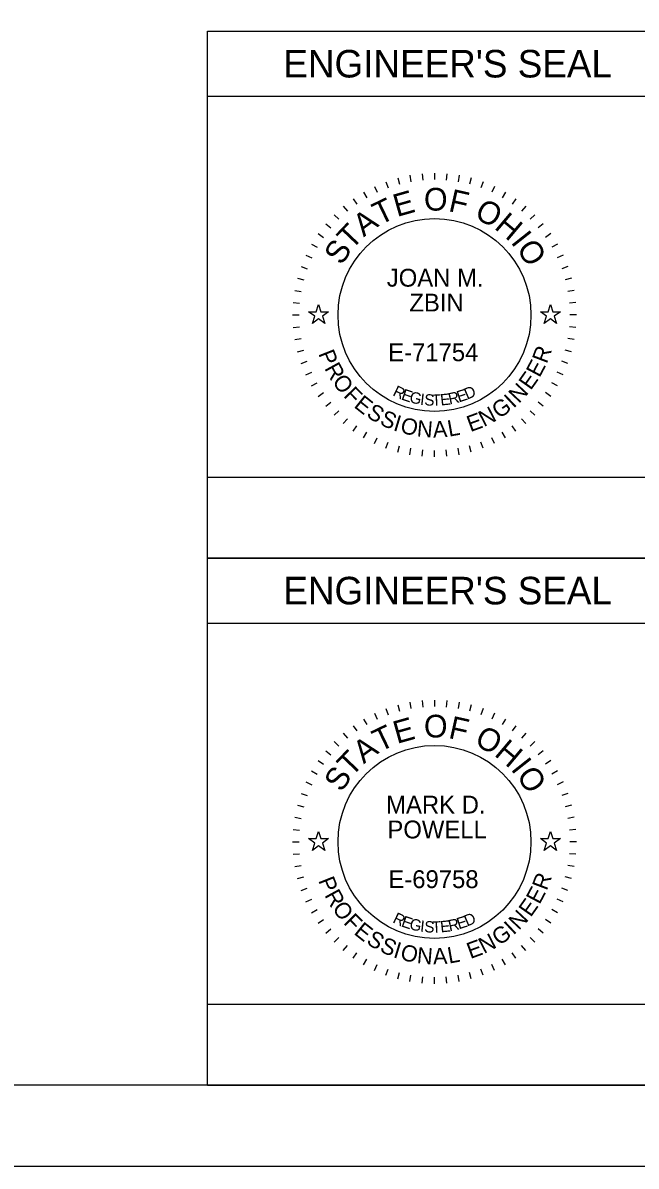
# Model space of a CAD drawing. Extents: x -6.1 to 38, y -7.7 to 22.
# Drawn here: x 7.31 to 11.09, y 0 to 7.05 of the extents above; entities that cross this region are included whole.
import ezdxf

# ---------------------------------------------------------------- set-up
doc = ezdxf.new("R2010")
doc.units = 0
for name, color, linetype in [('Default', 7, 'Continuous'), ('SH_Border', 7, 'Continuous'), ('SH_Cut_Line', 7, 'Continuous'), ('SH_Data', 7, 'Continuous')]:
    doc.layers.add(name, color=color, linetype=linetype)

msp = doc.modelspace()

# ---------------------------------------------------------------- linework, layer by layer
at = {"layer": 'Default'}
for points in [[(9.0736, 5.27), (9.1205, 5.27), (9.135, 5.3145), (9.1495, 5.27), (9.1964, 5.27), (9.1585, 5.2424), (9.173, 5.1978), (9.135, 5.2254), (9.097, 5.1978), (9.1115, 5.2424)], [(10.5036, 5.27), (10.5505, 5.27), (10.565, 5.3145), (10.5795, 5.27), (10.6264, 5.27), (10.5885, 5.2424), (10.603, 5.1978), (10.565, 5.2254), (10.527, 5.1978), (10.5415, 5.2424)], [(9.0736, 2.02), (9.1205, 2.02), (9.135, 2.0645), (9.1495, 2.02), (9.1964, 2.02), (9.1585, 1.9924), (9.173, 1.9478), (9.135, 1.9754), (9.097, 1.9478), (9.1115, 1.9924)], [(10.5036, 2.02), (10.5505, 2.02), (10.565, 2.0645), (10.5795, 2.02), (10.6264, 2.02), (10.5885, 1.9924), (10.603, 1.9478), (10.565, 1.9754), (10.527, 1.9478), (10.5415, 1.9924)]]:
    msp.add_lwpolyline(points, close=True, dxfattribs=at)
at = {"layer": 'SH_Border'}
msp.add_lwpolyline([(1.5, 21.5), (33.5, 21.5), (33.5, 0.5), (1.5, 0.5)], close=True, dxfattribs=at)
at = {"layer": 'SH_Cut_Line'}
msp.add_lwpolyline([(0, 0), (34, 0), (34, 22), (0, 22)], close=True, dxfattribs=at)
at = {"layer": 'SH_Data'}
for p, q in [((8.45, 3.75), (8.45, 7)), ((8.45, 7), (11.25, 7)), ((8.45, 6.6), (11.25, 6.6)), ((9.5507, 6.0722), (9.5644, 6.0346)), ((9.6235, 6.0952), (9.6339, 6.0565)), ((9.6981, 6.1117), (9.705, 6.0723)), ((9.7737, 6.1217), (9.7772, 6.0818)), ((9.85, 6.125), (9.85, 6.085)), ((9.9263, 6.1217), (9.9228, 6.0818)), ((10.0019, 6.1117), (9.995, 6.0723)), ((10.0765, 6.0952), (10.0661, 6.0565)), ((10.1493, 6.0722), (10.1356, 6.0346)), ((9.4125, 6.0078), (9.4325, 5.9731)), ((9.4802, 6.043), (9.4971, 6.0068)), ((10.2198, 6.043), (10.2029, 6.0068)), ((10.2875, 6.0078), (10.2675, 5.9731)), ((9.3481, 5.9668), (9.3711, 5.934)), ((10.3519, 5.9668), (10.3289, 5.934)), ((9.2313, 5.8687), (9.2596, 5.8404)), ((9.2876, 5.9203), (9.3133, 5.8896)), ((10.4124, 5.9203), (10.3867, 5.8896)), ((10.4687, 5.8687), (10.4404, 5.8404)), ((9.1797, 5.8124), (9.2104, 5.7867)), ((10.5203, 5.8124), (10.4896, 5.7867)), ((9.1332, 5.7519), (9.166, 5.7289)), ((10.5668, 5.7519), (10.534, 5.7289)), ((9.0922, 5.6875), (9.1269, 5.6675)), ((10.6078, 5.6875), (10.5731, 5.6675)), ((9.057, 5.6198), (9.0932, 5.6029)), ((10.643, 5.6198), (10.6068, 5.6029)), ((9.0278, 5.5493), (9.0654, 5.5356)), ((10.6722, 5.5493), (10.6346, 5.5356)), ((9.0048, 5.4765), (9.0435, 5.4661)), ((10.6952, 5.4765), (10.6565, 5.4661)), ((8.9883, 5.4019), (9.0277, 5.395)), ((10.7117, 5.4019), (10.6723, 5.395)), ((8.9783, 5.3263), (9.0182, 5.3228)), ((10.7217, 5.3263), (10.6818, 5.3228)), ((8.975, 5.25), (9.015, 5.25)), ((10.725, 5.25), (10.685, 5.25)), ((8.9783, 5.1737), (9.0182, 5.1772)), ((10.7217, 5.1737), (10.6818, 5.1772)), ((8.9883, 5.0981), (9.0277, 5.105)), ((10.7117, 5.0981), (10.6723, 5.105)), ((9.0048, 5.0235), (9.0435, 5.0339)), ((10.6952, 5.0235), (10.6565, 5.0339)), ((9.0278, 4.9507), (9.0654, 4.9644)), ((10.6722, 4.9507), (10.6346, 4.9644)), ((9.057, 4.8802), (9.0932, 4.8971)), ((10.643, 4.8802), (10.6068, 4.8971)), ((9.0922, 4.8125), (9.1269, 4.8325)), ((10.6078, 4.8125), (10.5731, 4.8325)), ((9.1332, 4.7481), (9.166, 4.7711)), ((10.5668, 4.7481), (10.534, 4.7711)), ((9.1797, 4.6876), (9.2104, 4.7133)), ((9.2313, 4.6313), (9.2596, 4.6596)), ((10.4687, 4.6313), (10.4404, 4.6596)), ((10.5203, 4.6876), (10.4896, 4.7133)), ((9.2876, 4.5797), (9.3133, 4.6104)), ((10.4124, 4.5797), (10.3867, 4.6104)), ((9.3481, 4.5332), (9.3711, 4.566)), ((9.4125, 4.4922), (9.4325, 4.5269)), ((10.2875, 4.4922), (10.2675, 4.5269)), ((10.3519, 4.5332), (10.3289, 4.566)), ((9.4802, 4.457), (9.4971, 4.4932)), ((9.5507, 4.4278), (9.5644, 4.4654)), ((9.6235, 4.4048), (9.6339, 4.4435)), ((10.0765, 4.4048), (10.0661, 4.4435)), ((10.1493, 4.4278), (10.1356, 4.4654)), ((10.2198, 4.457), (10.2029, 4.4932)), ((9.6981, 4.3883), (9.705, 4.4277)), ((9.7737, 4.3783), (9.7772, 4.4182)), ((9.85, 4.375), (9.85, 4.415)), ((9.9263, 4.3783), (9.9228, 4.4182)), ((10.0019, 4.3883), (9.995, 4.4277)), ((8.45, 3.75), (11.25, 3.75)), ((8.45, 3.75), (11.25, 3.75)), ((8.45, 0.5), (8.45, 3.75)), ((8.45, 3.75), (11.25, 3.75)), ((8.45, 3.35), (11.25, 3.35)), ((9.5507, 2.8222), (9.5644, 2.7846)), ((9.6235, 2.8452), (9.6339, 2.8065)), ((9.6981, 2.8617), (9.705, 2.8223)), ((9.7737, 2.8717), (9.7772, 2.8318)), ((9.85, 2.875), (9.85, 2.835)), ((9.9263, 2.8717), (9.9228, 2.8318)), ((10.0019, 2.8617), (9.995, 2.8223)), ((10.0765, 2.8452), (10.0661, 2.8065)), ((10.1493, 2.8222), (10.1356, 2.7846)), ((9.4125, 2.7578), (9.4325, 2.7231)), ((9.4802, 2.793), (9.4971, 2.7568)), ((10.2198, 2.793), (10.2029, 2.7568)), ((10.2875, 2.7578), (10.2675, 2.7231)), ((9.3481, 2.7168), (9.3711, 2.684)), ((10.3519, 2.7168), (10.3289, 2.684)), ((9.2313, 2.6187), (9.2596, 2.5904)), ((9.2876, 2.6703), (9.3133, 2.6396)), ((10.4124, 2.6703), (10.3867, 2.6396)), ((10.4687, 2.6187), (10.4404, 2.5904)), ((9.1797, 2.5624), (9.2104, 2.5367)), ((10.5203, 2.5624), (10.4896, 2.5367)), ((9.1332, 2.5019), (9.166, 2.4789)), ((10.5668, 2.5019), (10.534, 2.4789)), ((9.0922, 2.4375), (9.1269, 2.4175)), ((10.6078, 2.4375), (10.5731, 2.4175)), ((9.057, 2.3698), (9.0932, 2.3529)), ((10.643, 2.3698), (10.6068, 2.3529)), ((9.0278, 2.2993), (9.0654, 2.2856)), ((10.6722, 2.2993), (10.6346, 2.2856)), ((9.0048, 2.2265), (9.0435, 2.2161)), ((10.6952, 2.2265), (10.6565, 2.2161)), ((8.9883, 2.1519), (9.0277, 2.145)), ((10.7117, 2.1519), (10.6723, 2.145)), ((8.9783, 2.0763), (9.0182, 2.0728)), ((10.7217, 2.0763), (10.6818, 2.0728)), ((8.975, 2), (9.015, 2)), ((10.725, 2), (10.685, 2)), ((8.9783, 1.9237), (9.0182, 1.9272)), ((10.7217, 1.9237), (10.6818, 1.9272)), ((8.9883, 1.8481), (9.0277, 1.855)), ((10.7117, 1.8481), (10.6723, 1.855)), ((9.0048, 1.7735), (9.0435, 1.7839)), ((10.6952, 1.7735), (10.6565, 1.7839)), ((9.0278, 1.7007), (9.0654, 1.7144)), ((10.6722, 1.7007), (10.6346, 1.7144)), ((9.057, 1.6302), (9.0932, 1.6471)), ((10.643, 1.6302), (10.6068, 1.6471)), ((9.0922, 1.5625), (9.1269, 1.5825)), ((10.6078, 1.5625), (10.5731, 1.5825)), ((9.1332, 1.4981), (9.166, 1.5211)), ((10.5668, 1.4981), (10.534, 1.5211)), ((9.1797, 1.4376), (9.2104, 1.4633)), ((10.5203, 1.4376), (10.4896, 1.4633)), ((9.2313, 1.3813), (9.2596, 1.4096)), ((9.2876, 1.3297), (9.3133, 1.3604)), ((10.4124, 1.3297), (10.3867, 1.3604)), ((10.4687, 1.3813), (10.4404, 1.4096)), ((9.3481, 1.2832), (9.3711, 1.316)), ((9.4125, 1.2422), (9.4325, 1.2769)), ((10.2875, 1.2422), (10.2675, 1.2769)), ((10.3519, 1.2832), (10.3289, 1.316)), ((9.4802, 1.207), (9.4971, 1.2432)), ((9.5507, 1.1778), (9.5644, 1.2154)), ((10.1493, 1.1778), (10.1356, 1.2154)), ((10.2198, 1.207), (10.2029, 1.2432)), ((9.6235, 1.1548), (9.6339, 1.1935)), ((9.6981, 1.1383), (9.705, 1.1777)), ((9.7737, 1.1283), (9.7772, 1.1682)), ((9.85, 1.125), (9.85, 1.165)), ((9.9263, 1.1283), (9.9228, 1.1682)), ((10.0019, 1.1383), (9.995, 1.1777)), ((10.0765, 1.1548), (10.0661, 1.1935)), ((8.45, 0.5), (11.25, 0.5))]:
    msp.add_line(p, q, dxfattribs=at)
for points in [[(8.45, 3.75), (8.45, 4.25), (11.25, 4.25), (11.25, 3.75)], [(8.45, 0.5), (8.45, 1), (11.25, 1), (11.25, 0.5)]]:
    msp.add_lwpolyline(points, close=True, dxfattribs=at)
for centre in [(9.85, 5.25), (9.85, 2)]:
    msp.add_circle(centre, 0.595, dxfattribs=at)

# ---------------------------------------------------------------- texts
for s, height, p in [("ENGINEER'S SEAL", 0.17, (8.9176, 6.715)), ('JOAN M.', 0.11, (9.5559, 5.4249)), ('ZBIN', 0.11, (9.695, 5.2716)), ('E-71754', 0.11, (9.5645, 4.9651)), ("ENGINEER'S SEAL", 0.17, (8.9176, 3.465)), ('MARK D.', 0.11, (9.5518, 2.1749)), ('POWELL', 0.11, (9.5597, 2.0216)), ('E-69758', 0.11, (9.5657, 1.7151))]:
    msp.add_text(s, height=height, dxfattribs=at).set_placement(p)
for s, height, rotation, p in [('E', 0.14, 15.75706, (9.6184, 5.8538)), ('O', 0.14, 359.78119, (9.7847, 5.8943)), ('F', 0.14, 347.43619, (9.9311, 5.8917)), ('T', 0.14, 25.71674, (9.5116, 5.8018)), ('O', 0.14, 332.25863, (10.0898, 5.8515)), ('A', 0.14, 36.47472, (9.4134, 5.7281)), ('H', 0.14, 319.91363, (10.2132, 5.7861)), ('T', 0.14, 46.4344, (9.3383, 5.6464)), ('I', 0.14, 308.36695, (10.3165, 5.6983)), ('S', 0.14, 57.19238, (9.2781, 5.5514)), ('O', 0.14, 303.14906, (10.3521, 5.6589)), ('P', 0.1, 291.49398, (9.1323, 5.0121)), ('R', 0.1, 69.23216, (10.5419, 4.9454)), ('R', 0.1, 298.73106, (9.169, 4.9217)), ('E', 0.1, 61.99508, (10.4976, 4.8598)), ('O', 0.1, 306.46664, (9.2155, 4.8383)), ('E', 0.1, 54.75801, (10.4433, 4.7814)), ('F', 0.1, 314.7068, (9.2843, 4.7483)), ('R', 0.07, 334.48695, (9.5875, 4.7551)), ('D', 0.07, 23.30524, (10.051, 4.727)), ('N', 0.1, 47.02243, (10.3702, 4.7008)), ('E', 0.1, 321.43929, (9.3478, 4.6848)), ('E', 0.07, 341.03996, (9.6406, 4.7301)), ('G', 0.07, 347.47515, (9.6914, 4.7118)), ('I', 0.07, 353.78581, (9.7591, 4.6968)), ('S', 0.07, 356.89262, (9.7858, 4.6929)), ('T', 0.07, 3.00609, (9.8357, 4.6887)), ('E', 0.07, 6.01169, (9.8889, 4.6912)), ('R', 0.07, 11.91844, (9.9425, 4.6974)), ('E', 0.07, 17.68363, (9.9998, 4.7102)), ('G', 0.1, 35.04687, (10.2481, 4.607)), ('I', 0.1, 43.28703, (10.3368, 4.6714)), ('S', 0.1, 328.67637, (9.4243, 4.6252)), ('S', 0.1, 335.91345, (9.5064, 4.5766)), ('N', 0.1, 27.31129, (10.1545, 4.5575)), ('I', 0.1, 343.15053, (9.5906, 4.5397)), ('O', 0.1, 346.88592, (9.6339, 4.5251)), ('N', 0.1, 355.12608, (9.7388, 4.5017)), ('A', 0.1, 2.86166, (9.8423, 4.4937)), ('L', 0.1, 10.09874, (9.9394, 4.499)), ('E', 0.1, 20.07421, (10.0712, 4.527)), ('E', 0.14, 15.75706, (9.6184, 2.6038)), ('O', 0.14, 359.78119, (9.7847, 2.6443)), ('F', 0.14, 347.43619, (9.9311, 2.6417)), ('T', 0.14, 25.71674, (9.5116, 2.5518)), ('O', 0.14, 332.25863, (10.0898, 2.6015)), ('A', 0.14, 36.47472, (9.4134, 2.4781)), ('H', 0.14, 319.91363, (10.2132, 2.5361)), ('T', 0.14, 46.4344, (9.3383, 2.3964)), ('I', 0.14, 308.36695, (10.3165, 2.4483)), ('S', 0.14, 57.19238, (9.2781, 2.3014)), ('O', 0.14, 303.14906, (10.3521, 2.4089)), ('P', 0.1, 291.49398, (9.1323, 1.7621)), ('R', 0.1, 69.23216, (10.5419, 1.6954)), ('R', 0.1, 298.73106, (9.169, 1.6717)), ('E', 0.1, 61.99508, (10.4976, 1.6098)), ('O', 0.1, 306.46664, (9.2155, 1.5883)), ('E', 0.1, 54.75801, (10.4433, 1.5314)), ('F', 0.1, 314.7068, (9.2843, 1.4983)), ('R', 0.07, 334.48695, (9.5875, 1.5051)), ('D', 0.07, 23.30524, (10.051, 1.477)), ('N', 0.1, 47.02243, (10.3702, 1.4508)), ('E', 0.1, 321.43929, (9.3478, 1.4348)), ('E', 0.07, 341.03996, (9.6406, 1.4801)), ('G', 0.07, 347.47515, (9.6914, 1.4618)), ('I', 0.07, 353.78581, (9.7591, 1.4468)), ('S', 0.07, 356.89262, (9.7858, 1.4429)), ('T', 0.07, 3.00609, (9.8357, 1.4387)), ('E', 0.07, 6.01169, (9.8889, 1.4412)), ('R', 0.07, 11.91844, (9.9425, 1.4474)), ('E', 0.07, 17.68363, (9.9998, 1.4602)), ('I', 0.1, 43.28703, (10.3368, 1.4214)), ('S', 0.1, 328.67637, (9.4243, 1.3752)), ('N', 0.1, 27.31129, (10.1545, 1.3075)), ('G', 0.1, 35.04687, (10.2481, 1.357)), ('S', 0.1, 335.91345, (9.5064, 1.3266)), ('I', 0.1, 343.15053, (9.5906, 1.2897)), ('O', 0.1, 346.88592, (9.6339, 1.2751)), ('N', 0.1, 355.12608, (9.7388, 1.2517)), ('A', 0.1, 2.86166, (9.8423, 1.2437)), ('L', 0.1, 10.09874, (9.9394, 1.249)), ('E', 0.1, 20.07421, (10.0712, 1.277))]:
    msp.add_text(s, height=height, rotation=rotation, dxfattribs=at).set_placement(p)

doc.saveas('drawing.dxf')
